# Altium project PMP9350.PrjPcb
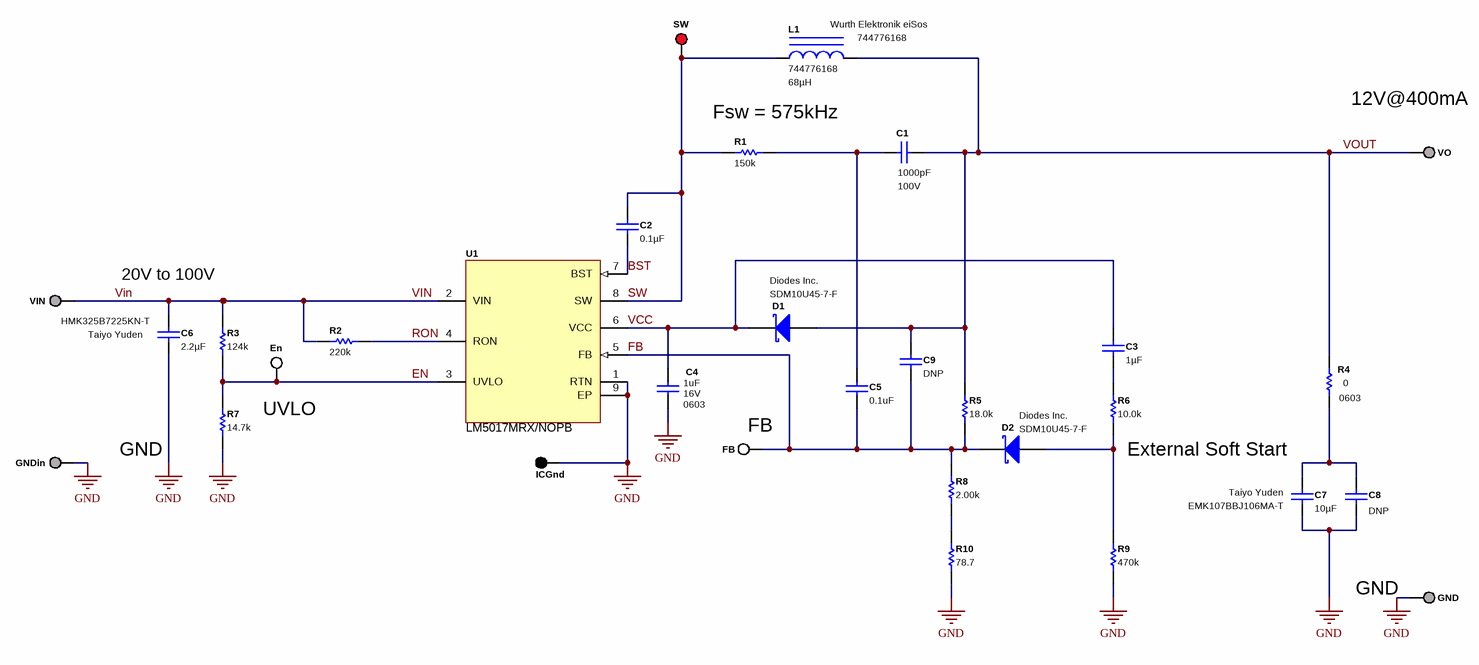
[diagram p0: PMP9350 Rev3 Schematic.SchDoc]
TID: PMP9350; TechSupport: http://www.ti.com/support; SCH_Rev: 1; PRJ_Title: LM5017 Sync Buck; PRJ_Number: PMP9350; PRJ_Engineer: David Baba; PRJ_Customer: Public Release; PCB_Rev: 3; PCB_Layout: David Baba; EVM_Orderable: N/A; CopyrightYear: 2014
2 sheets, 36 parts. Net scope: global (net labels, ports and power ports of the same name join across sheets).
Board file: PMP9350.PcbDoc
Sheets:
  PMP9350 Rev3 Schematic.SchDoc
  PMP9350_Hardware.SchDoc

## Sheet PMP9350 Rev3 Schematic.SchDoc
size 431 x 279 mm; DocumentNumber: 1; SheetNumber: 1; SheetTotal: 2; PageSetup: Record=PageOptions¦CenterHorizontal=True¦CenterVertical=True¦PrintScale=0.62¦XCorrection=1.00¦YCorrection=1.00¦PrintKind=0¦BorderSize=5000000¦LeftOffset=0¦BottomOffset=0¦Orientation=2¦PaperLength=1000¦PaperWidth=1000¦Scale=100¦PaperSource=15¦PrintQuality=600¦MediaType=1¦DitherType=10¦PaperKind=Letter¦PrintScaleMode=1

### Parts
C1  ValueDisplayed: 1000pF  Value2: 100V  [0603L]  (hidden comment: GRM188R72A102KA01D)
C2  ValueDisplayed: 0.1µF  [0603L]  (hidden comment: 06035C104KAT2A)
C3  ValueDisplayed: 1µF  [0603L]  (hidden comment: GRM188R71E105KA12D)
C4  value 1uF  PackageReference: 0603  Value2: 16V  [0603L]  (hidden comment: C0603C105K4PACTU)
C5  ValueDisplayed: 0.1uF  [0402L]  (hidden comment: GRM155R71C102KA01D)
C6  ValueDisplayed: 2.2µF  Manufacturer: Taiyo Yuden  [1210L]  (hidden comment: HMK325B7225KN-T)
C7  ValueDisplayed: 10µF  Manufacturer: Taiyo Yuden  [0603L]  (hidden comment: EMK107BBJ106MA-T)
C8  DNP  [0603L]
C9  ValueDisplayed: DNP  [0603L]  (hidden comment: GRM188R71C103KA01D)
D1  Manufacturer: Diodes Inc.  [SOD-523]
D2  Manufacturer: Diodes Inc.  [SOD-523]
En  5002  [Keystone5002]  (value not drawn)
FB  5002  [Keystone5002]  (value not drawn)
GND  Suggest using a net name here  [Keystone1502-2]  (value not drawn)
GNDin  Suggest using a net name here  [Keystone1502-2]  (value not drawn)
ICGnd  5001  [Keystone5001]  (value not drawn)
L1  744776168  ValueDisplayed: 68µH  Manufacturer: Wurth Elektronik eiSos  [WE-PD2-XL]
R1  value 150k  [0603L]  (hidden comment: CRCW0603150KFKEA)
R2  value 220k  [0603L]  (hidden comment: CRCW0603220KJNEA)
R3  value 124k  [0603L]  (hidden comment: CRCW0603124KFKEA)
R4  value 0  PackageReference: 0603  [0402L]  (hidden comment: CRCW06030000Z0EA)
R5  value 18.0k  [0603L]  (hidden comment: RC0603FR-0718KL)
R6  value 10.0k  [0603L]  (hidden comment: CRCW060310K0FKEA)
R7  value 14.7k  [0603L]  (hidden comment: CRCW060314K7FKEA)
R8  value 2.00k  [0603L]  (hidden comment: CRCW06032K00FKEA)
R9  value 470k  [0603L]  (hidden comment: CRCW0603470KJNEA)
R10  value 78.7  [0603L]  (hidden comment: CRCW060378R7FKEA)
SW  5000  [Keystone5000]  (value not drawn)
U1  LM5017MRX/NOPB  [DDA0008B_N]
VIN  Suggest using a net name here  [Keystone1502-2]  (value not drawn)
VO  Suggest using a net name here  [Keystone1502-2]  (value not drawn)

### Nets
GND: C4.2 C6.2 C7.2 C8.2 GND.1 GNDin.1 ICGnd.1 R7.1 R9.1 R10.1 U1.1(RTN) U1.9(EP)
BST: C2.2 U1.7(BST)
EN: En.1 R3.1 R7.2 U1.3(UVLO)
FB: C5.2 C9.2 D2.1(K) FB.1 R5.1 R8.2 U1.5(FB)
RON: R2.2 U1.4(RON)
SW: C2.1 L1.1 R1.1 SW.1 U1.8(SW)
VCC: C3.1 C4.1 D1.1(K) U1.6(VCC)
Vin: C6.1 R2.1 R3.2 U1.2(VIN) VIN.1
VOUT: C1.1 C9.1 D1.2(A) L1.2 R4.2 R5.2 VO.1
NetC1_2: C1.2 C5.1 R1.2
NetC3_2: C3.2 R6.2
NetC7_1: C7.1 C8.1 R4.1
NetD2_2: D2.2(A) R6.1 R9.2
NetR8_1: R8.1 R10.2

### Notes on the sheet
- Fsw = 575kHz
- (near VO) 12V@400mA
- 20V to 100V
- GND
- UVLO
- (near FB) FB
- (near R6) External Soft Start
- (near GND) GND

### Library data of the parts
C1 = GRM188R72A102KA01D: CAP, CERM, 1000pF, 100V, +/-10%, X7R, 0603; Manufacturer: MuRata; Polarized: N; CompType: Capacitor; U/M: EA; Cap_F: 0.000000001; Tolerance_%: 10; Value1: Unknown; VDC_V: 100; TaMin_C: -55; TaMax_C: 125; Cap_Case: 0603
C2 = 06035C104KAT2A: CAP, CERM, 0.1uF, 50V, +/-10%, X7R, 0603; Manufacturer: AVX; Polarized: N; CompType: Capacitor; U/M: EA; Cap_F: 0.0000001; Tolerance_%: 10; Value1: Unknown; VDC_V: 50; TaMin_C: -55; TaMax_C: 125; Cap_Case: 0603
C3 = GRM188R71E105KA12D: CAP, CERM, 1uF, 25V, +/-10%, X7R, 0603; Manufacturer: MuRata; Polarized: N; CompType: Capacitor; U/M: EA; Cap_F: 0.000001; Tolerance_%: 10; Value1: Unknown; VDC_V: 25; TaMin_C: -55; TaMax_C: 125; Cap_Case: 0603
C4 = C0603C105K4PACTU: CAP, CERM, 1uF, 16V, +/-10%, X5R, 0603; Manufacturer: Kemet; Polarized: N; TaMax_C: 85; TaMin_C: -55; Tolerance_%: 10; VDC_V: 16; Cap_F: 0.000001; CompType: Capacitor; ValueDisplayed: 1µF; U/M: EA
C5 = GRM155R71C102KA01D: CAP, CERM, 1000pF, 16V, +/-10%, X7R, 0402; Manufacturer: MuRata; Polarized: N; CompType: Capacitor; U/M: EA; Cap_F: 0.000000001; Tolerance_%: 10; Value1: Unknown; VDC_V: 16; TaMin_C: -55; TaMax_C: 125; Cap_Case: 0402
C6 = HMK325B7225KN-T: CAP, CERM, 2.2uF, 100V, +/-10%, X7R, 1210; Polarized: N; CompType: Capacitor; U/M: EA; Cap_F: 0.0000022; Tolerance_%: 10; Value1: Unknown; VDC_V: 100; TaMin_C: -55; TaMax_C: 125; Cap_Case: 1210
C7 = EMK107BBJ106MA-T: CAP, CERM, 10uF, 16V, +/-20%, X5R, 0603; Polarized: N; CompType: Capacitor; U/M: EA; Cap_F: 0.00001; Tolerance_%: 20; Value1: Unknown; VDC_V: 16; TaMin_C: -55; TaMax_C: 85; Cap_Case: 0603
C8 = GRM21BR71E225KA73L: CAP, CERM, 2.2uF, 25V, +/-10%, X7R, 0805; Manufacturer: MuRata; Polarized: N; CompType: Capacitor; U/M: EA; Cap_F: 0.0000022; Tolerance_%: 10; ESR_Ohm: 0.005; Value1: 0.005 ohm; VDC_V: 25; TaMin_C: -55; TaMax_C: 125; Cap_Case: 0805
C9 = GRM188R71C103KA01D: CAP, CERM, 0.01uF, 16V, +/-10%, X7R, 0603; Manufacturer: MuRata; Polarized: N; CompType: Capacitor; U/M: EA; Cap_F: 0.00000001; Tolerance_%: 10; Value1: Unknown; VDC_V: 16; TaMin_C: -55; TaMax_C: 125; Cap_Case: 0603
D1 D2 = SDM10U45-7-F: Diode, Schottky, 45V, 0.1A, SOD-523; Vf_V: 0.58; Io_A: 0.1; Vr_V: 45; TJMax_C: 125; Value: 0.58V; U/M: EA
En = 5002: Test Point, TH, Miniature, White; Manufacturer: Keystone; CompType: Test Point Loop; U/M: EA
FB = 5002: Test Point, TH, Miniature, White; Manufacturer: Keystone; Alternate Manufacturer: Any; Alternate PartNumber: Equivalent; CompType: Test Point Loop; U/M: EA
GND GNDin VIN VO = 1502-2: Terminal, Turret, TH, Double; Manufacturer: Keystone; CompType: Turret Terminal; U/M: EA
ICGnd = 5001: Test Point, TH, Miniature, Black; Manufacturer: Keystone; CompType: Test Point Loop; U/M: EA
L1 = 744776168: Inductor, Drum Core, Ferrite, 68uH, 1.19A, 0.138 ohm, SMD; Ind_H: 68.0E-6; Imax_A: 1.19; Irms: 1.19A @ 40C rise; Isat: 1.49A @ 10% inductance drop; DCR_ohm: 0.138; U/M: EA
R1 = CRCW0603150KFKEA: RES, 150k ohm, 1%, 0.1W, 0603; Manufacturer: Vishay-Dale; CompType: Resistor; Res_ohm: 150000; Tolerance_%: 1; Power_W: 0.1; VDC_V: 75; TempCo: 100 ppm/C; EIA_Code: E96; U/M: EA
R2 = CRCW0603220KJNEA: RES, 220k ohm, 5%, 0.1W, 0603; Manufacturer: Vishay-Dale; CompType: Resistor; Res_ohm: 220000; Tolerance_%: 5; Power_W: 0.1; VDC_V: 75; TempCo: 200 ppm/C; EIA_Code: E24; U/M: EA
R3 = CRCW0603124KFKEA: RES, 124k ohm, 1%, 0.1W, 0603; Manufacturer: Vishay-Dale; CompType: Resistor; Res_ohm: 124000; Tolerance_%: 1; Power_W: 0.1; VDC_V: 75; TempCo: 100 ppm/C; EIA_Code: E96; U/M: EA
R4 = CRCW06030000Z0EA: RES, 0 ohm, 5%, 0.1W, 0603; Manufacturer: Vishay-Dale; CompType: Resistor; Value_Code: 0000; Tolerance_%: 5; Power_W: 0.1; VDC_V: 75; TempCo: 200 ppm/C; EIA_Code: E24; U/M: EA
R5 = RC0603FR-0718KL: RES, 18.0k ohm, 1%, 0.1W, 0603; Manufacturer: Yageo America; CompType: Resistor; Res_ohm: 18000; Value_Code: 18k0; Tolerance_%: 1; Power_W: 0.1; VDC_V: 150; TempCo: 200 ppm/C; U/M: EA
R6 = CRCW060310K0FKEA: RES, 10.0k ohm, 1%, 0.1W, 0603; Manufacturer: Vishay-Dale; CompType: Resistor; Res_ohm: 10000; Value_Code: 10k0; Tolerance_%: 1; Power_W: 0.1; VDC_V: 75; TempCo: 100 ppm/C; EIA_Code: E96; U/M: EA
R7 = CRCW060314K7FKEA: RES, 14.7k ohm, 1%, 0.1W, 0603; Manufacturer: Vishay-Dale; CompType: Resistor; Res_ohm: 14700; Value_Code: 14k7; Tolerance_%: 1; Power_W: 0.1; VDC_V: 75; TempCo: 100 ppm/C; EIA_Code: E96; U/M: EA
R8 = CRCW06032K00FKEA: RES, 2.00k ohm, 1%, 0.1W, 0603; Manufacturer: Vishay-Dale; CompType: Resistor; Res_ohm: 2000; Value_Code: 2k00; Tolerance_%: 1; Power_W: 0.1; VDC_V: 75; TempCo: 100 ppm/C; EIA_Code: E96; U/M: EA
R9 = CRCW0603470KJNEA: RES, 470k ohm, 5%, 0.1W, 0603; Manufacturer: Vishay-Dale; CompType: Resistor; Res_ohm: 470000; Tolerance_%: 5; Power_W: 0.1; VDC_V: 75; TempCo: 200 ppm/C; EIA_Code: E24; U/M: EA
R10 = CRCW060378R7FKEA: RES, 78.7 ohm, 1%, 0.1W, 0603; Manufacturer: Vishay-Dale; CompType: Resistor; Value_Code: 78R7; Tolerance_%: 1; Power_W: 0.1; VDC_V: 75; TempCo: 100 ppm/C; EIA_Code: E96; U/M: EA
SW = 5000: Test Point, TH, Miniature, Red; Manufacturer: Keystone; CompType: Test Point Loop; U/M: EA
U1 = LM5017MRX/NOPB: 100V, 600mA Constant On-Time Synchronous Buck Regulator, DDA0008B; Manufacturer: Texas Instruments; Alternate PartNumber: LM5017MR/NOPB; SymbolCreator: a0412235; CompType: IC; U/M: EA

## Sheet PMP9350_Hardware.SchDoc
size 431 x 279 mm; Date: Not shown in title block; ApprovedBy: Not shown in title block; CheckedBy: Not shown in title block; Author: Not shown in title block; CompanyName: Not shown in title block; Engineer: Not shown in title block; Organization: Not shown in title block; Address1: Not shown in title block; Address2: Not shown in title block; Address3: Not shown in title block; Address4: Not shown in title block; DocumentNumber: 2; Revision: Use project parameter SCH_Rev; SheetNumber: 2; SheetTotal: 2; PageSetup: Record=PageOptions¦CenterHorizontal=True¦CenterVertical=True¦PrintScale=1.00¦XCorrection=1.00¦YCorrection=1.00¦PrintKind=0¦BorderSize=5000000¦LeftOffset=0¦BottomOffset=0¦Orientation=2¦PaperLength=1000¦PaperWidth=1000¦Scale=100¦PaperSource=15¦PrintQuality=600¦MediaType=1¦DitherType=10¦PaperKind=Letter¦PrintScaleMode=1
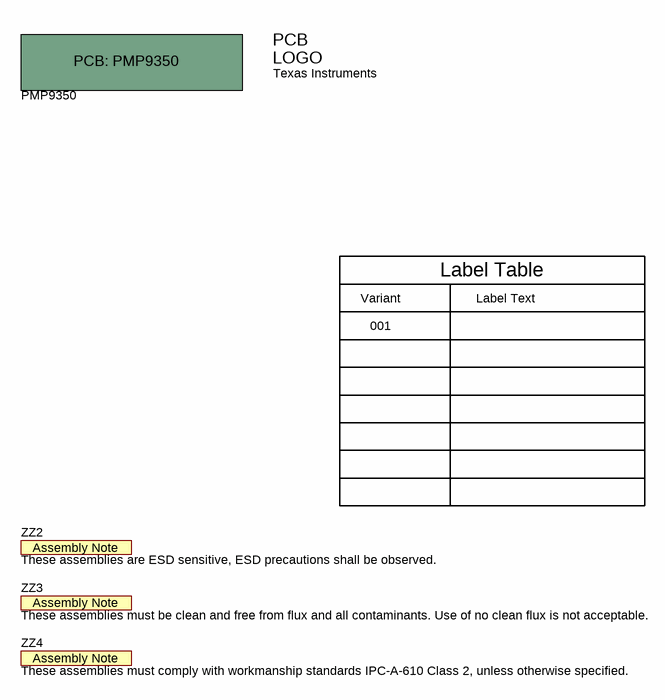
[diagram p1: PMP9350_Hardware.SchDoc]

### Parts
!PCB?  PMP9350  (mechanical)
Logo1  Texas Instruments  [TI_Stacked_SolderMask_Small]  (no BOM)
ZZ2  These assemblies are ESD sensitive, ESD precautions shall be observed.  [AssemblyNote]  (no BOM)
ZZ3  These assemblies must be clean and free from flux and all contaminants. Use of no clean flux is not acceptable.  [AssemblyNote]  (no BOM)
ZZ4  These assemblies must comply with workmanship standards IPC-A-610 Class 2, unless otherwise specified.  [AssemblyNote]  (no BOM)

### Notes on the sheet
- Variant
- Label Table
- Label Text
- 001

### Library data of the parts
!PCB? = PCB_OtherProject: Manufacturer: Any; SymbolCreator: a0412235; CompType: PCB; U/M: EA
Logo1 = TI_Logo: Texas Instrument Corporate Signature; SymbolCreator: codlsc
ZZ2-ZZ4 = AssemblyNote: SymbolCreator: codlsc

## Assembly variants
001: not fitted C8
